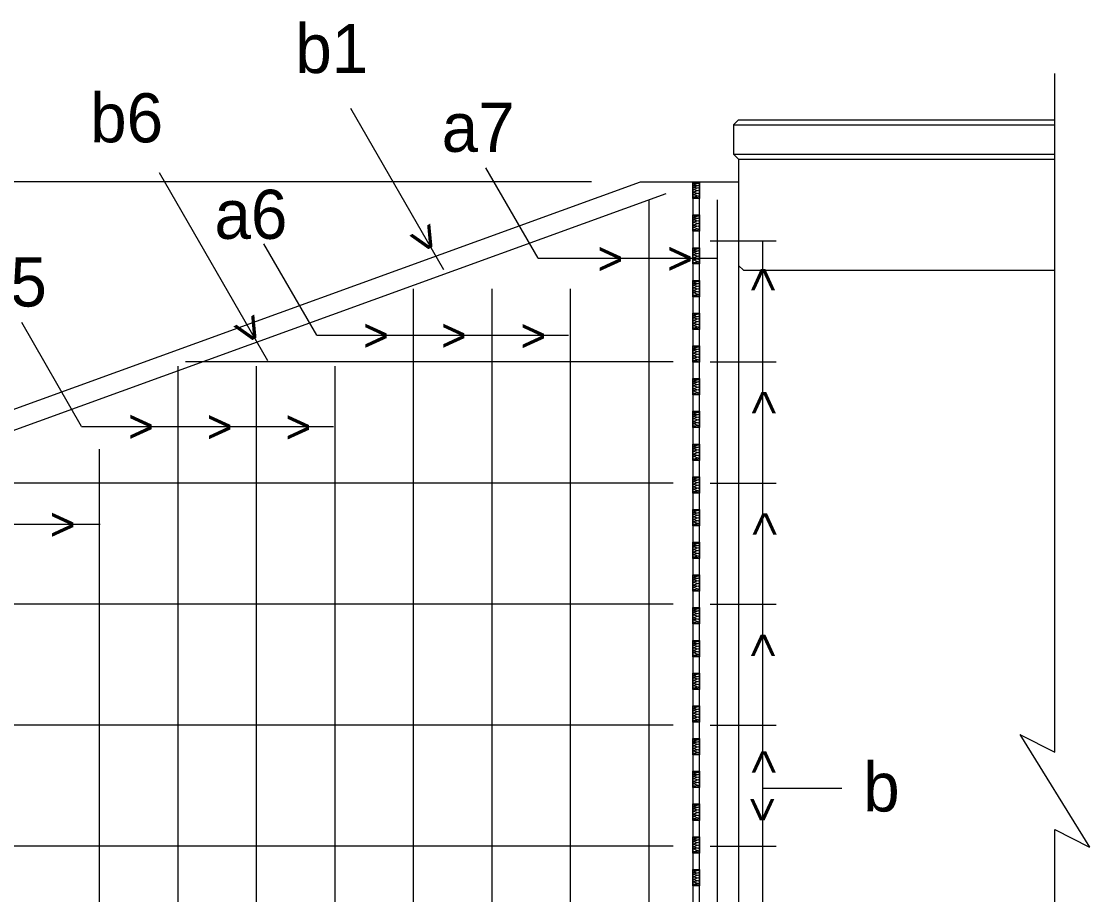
# Model space of a CAD drawing. Extents: x -0.08 to 2.83, y -0.03 to 1.92.
# Drawn here: x 0.6457 to 0.9292, y 0.8025 to 1.0342 of the extents above; entities that cross this region are included whole.
import ezdxf

# ---------------------------------------------------------------- set-up
doc = ezdxf.new("R2010")
doc.units = 0
for name, color, linetype in [('1', 7, 'Continuous'), ('50', 7, 'Continuous'), ('51', 7, 'Continuous'), ('55', 7, 'Continuous'), ('57', 7, 'Continuous')]:
    doc.layers.add(name, color=color, linetype=linetype)

msp = doc.modelspace()

# ---------------------------------------------------------------- linework, layer by layer
at = {"layer": '1'}
for points in [[(0.82387, 0.98719), (0.82387, 0.99152), (0.8256, 0.99152), (0.8256, 0.98719)], [(0.82387, 0.9785), (0.82387, 0.98284), (0.8256, 0.98284), (0.8256, 0.9785)], [(0.82387, 0.96983), (0.82387, 0.97416), (0.8256, 0.97416), (0.8256, 0.96983)], [(0.82387, 0.96114), (0.82387, 0.96548), (0.8256, 0.96548), (0.8256, 0.96114)], [(0.82387, 0.95246), (0.82387, 0.9568), (0.8256, 0.9568), (0.8256, 0.95246)], [(0.82387, 0.94379), (0.82387, 0.94812), (0.8256, 0.94812), (0.8256, 0.94379)], [(0.82387, 0.9351), (0.82387, 0.93944), (0.8256, 0.93944), (0.8256, 0.9351)], [(0.82387, 0.92642), (0.82387, 0.93076), (0.8256, 0.93076), (0.8256, 0.92642)], [(0.82387, 0.91774), (0.82387, 0.92208), (0.8256, 0.92208), (0.8256, 0.91774)], [(0.82387, 0.90906), (0.82387, 0.91339), (0.8256, 0.91339), (0.8256, 0.90906)], [(0.82387, 0.90038), (0.82387, 0.90472), (0.8256, 0.90472), (0.8256, 0.90038)], [(0.82387, 0.8917), (0.82387, 0.89604), (0.8256, 0.89604), (0.8256, 0.8917)], [(0.82387, 0.88302), (0.82387, 0.88735), (0.8256, 0.88735), (0.8256, 0.88302)], [(0.82387, 0.87434), (0.82387, 0.87868), (0.8256, 0.87868), (0.8256, 0.87434)], [(0.82387, 0.86566), (0.82387, 0.86999), (0.8256, 0.86999), (0.8256, 0.86566)], [(0.82387, 0.85698), (0.82387, 0.86131), (0.8256, 0.86131), (0.8256, 0.85698)], [(0.82387, 0.84829), (0.82387, 0.85264), (0.8256, 0.85264), (0.8256, 0.84829)], [(0.82387, 0.83962), (0.82387, 0.84395), (0.8256, 0.84395), (0.8256, 0.83962)], [(0.82387, 0.83094), (0.82387, 0.83527), (0.8256, 0.83527), (0.8256, 0.83094)], [(0.82387, 0.82225), (0.82387, 0.82659), (0.8256, 0.82659), (0.8256, 0.82225)], [(0.82387, 0.81358), (0.82387, 0.81791), (0.8256, 0.81791), (0.8256, 0.81358)], [(0.82387, 0.80489), (0.82387, 0.80923), (0.8256, 0.80923), (0.8256, 0.80489)]]:
    msp.add_lwpolyline(points, close=True, dxfattribs=at)
for points in [[(0.82398, 0.99128), (0.8255, 0.99129), (0.82398, 0.99078), (0.82534, 0.99066), (0.82402, 0.99025), (0.82531, 0.98999), (0.82405, 0.98958), (0.82526, 0.98929), (0.82405, 0.98884), (0.82536, 0.98851), (0.82401, 0.98827), (0.82536, 0.98778), (0.82409, 0.98754), (0.82531, 0.98743), (0.82524, 0.98741)], [(0.82398, 0.98259), (0.8255, 0.98261), (0.82398, 0.98209), (0.82534, 0.98198), (0.82402, 0.98157), (0.82531, 0.9813), (0.82405, 0.9809), (0.82526, 0.98061), (0.82405, 0.98016), (0.82536, 0.97983), (0.82401, 0.97959), (0.82536, 0.97909), (0.82409, 0.97886), (0.82531, 0.97874), (0.82524, 0.97873)], [(0.82398, 0.97392), (0.8255, 0.97394), (0.82398, 0.97341), (0.82534, 0.97329), (0.82402, 0.97289), (0.82531, 0.97263), (0.82405, 0.97222), (0.82526, 0.97193), (0.82405, 0.97148), (0.82536, 0.97115), (0.82401, 0.97091), (0.82536, 0.97042), (0.82409, 0.97018), (0.82531, 0.97006), (0.82524, 0.97004)], [(0.82398, 0.96524), (0.8255, 0.96525), (0.82398, 0.96474), (0.82534, 0.96462), (0.82402, 0.96421), (0.82531, 0.96394), (0.82405, 0.96354), (0.82526, 0.96324), (0.82405, 0.96279), (0.82536, 0.96247), (0.82401, 0.96223), (0.82536, 0.96174), (0.82409, 0.9615), (0.82531, 0.96139), (0.82524, 0.96137)], [(0.82398, 0.95655), (0.8255, 0.95657), (0.82398, 0.95605), (0.82534, 0.95594), (0.82402, 0.95553), (0.82531, 0.95526), (0.82405, 0.95486), (0.82526, 0.95457), (0.82405, 0.95412), (0.82536, 0.95379), (0.82401, 0.95355), (0.82536, 0.95305), (0.82409, 0.95282), (0.82531, 0.9527), (0.82524, 0.95269)], [(0.82398, 0.94788), (0.8255, 0.94789), (0.82398, 0.94737), (0.82534, 0.94725), (0.82402, 0.94685), (0.82531, 0.94659), (0.82405, 0.94618), (0.82526, 0.94589), (0.82405, 0.94544), (0.82536, 0.94511), (0.82401, 0.94487), (0.82536, 0.94438), (0.82409, 0.94414), (0.82531, 0.94402), (0.82524, 0.944)], [(0.82398, 0.93919), (0.8255, 0.93921), (0.82398, 0.93869), (0.82534, 0.93858), (0.82402, 0.93817), (0.82531, 0.9379), (0.82405, 0.9375), (0.82526, 0.9372), (0.82405, 0.93675), (0.82536, 0.93643), (0.82401, 0.93619), (0.82536, 0.93569), (0.82409, 0.93546), (0.82531, 0.93534), (0.82524, 0.93533)], [(0.82398, 0.93052), (0.8255, 0.93054), (0.82398, 0.93001), (0.82534, 0.92989), (0.82402, 0.92949), (0.82531, 0.92922), (0.82405, 0.92882), (0.82526, 0.92853), (0.82405, 0.92808), (0.82536, 0.92774), (0.82401, 0.92751), (0.82536, 0.92702), (0.82409, 0.92678), (0.82531, 0.92666), (0.82524, 0.92664)], [(0.82398, 0.92184), (0.8255, 0.92185), (0.82398, 0.92133), (0.82534, 0.92121), (0.82402, 0.92081), (0.82531, 0.92054), (0.82405, 0.92014), (0.82526, 0.91984), (0.82405, 0.91939), (0.82536, 0.91907), (0.82401, 0.91883), (0.82536, 0.91834), (0.82409, 0.91809), (0.82531, 0.91798), (0.82524, 0.91796)], [(0.82398, 0.91315), (0.8255, 0.91317), (0.82398, 0.91265), (0.82534, 0.91254), (0.82402, 0.91213), (0.82531, 0.91186), (0.82405, 0.91146), (0.82526, 0.91116), (0.82405, 0.91071), (0.82536, 0.91039), (0.82401, 0.91014), (0.82536, 0.90965), (0.82409, 0.90942), (0.82531, 0.9093), (0.82524, 0.90929)], [(0.82398, 0.90448), (0.8255, 0.90449), (0.82398, 0.90397), (0.82534, 0.90385), (0.82402, 0.90344), (0.82531, 0.90318), (0.82405, 0.90278), (0.82526, 0.90249), (0.82405, 0.90204), (0.82536, 0.9017), (0.82401, 0.90147), (0.82536, 0.90098), (0.82409, 0.90074), (0.82531, 0.90062), (0.82524, 0.9006)], [(0.82398, 0.89579), (0.8255, 0.89581), (0.82398, 0.89529), (0.82534, 0.89517), (0.82402, 0.89477), (0.82531, 0.8945), (0.82405, 0.89409), (0.82526, 0.8938), (0.82405, 0.89335), (0.82536, 0.89303), (0.82401, 0.89279), (0.82536, 0.89229), (0.82409, 0.89205), (0.82531, 0.89194), (0.82524, 0.89192)], [(0.82398, 0.88711), (0.8255, 0.88713), (0.82398, 0.88661), (0.82534, 0.88649), (0.82402, 0.88609), (0.82531, 0.88582), (0.82405, 0.88542), (0.82526, 0.88512), (0.82405, 0.88467), (0.82536, 0.88434), (0.82401, 0.8841), (0.82536, 0.88361), (0.82409, 0.88338), (0.82531, 0.88326), (0.82524, 0.88324)], [(0.82398, 0.87844), (0.8255, 0.87845), (0.82398, 0.87793), (0.82534, 0.87781), (0.82402, 0.8774), (0.82531, 0.87714), (0.82405, 0.87674), (0.82526, 0.87644), (0.82405, 0.87599), (0.82536, 0.87566), (0.82401, 0.87543), (0.82536, 0.87494), (0.82409, 0.87469), (0.82531, 0.87458), (0.82524, 0.87456)], [(0.82398, 0.86975), (0.8255, 0.86977), (0.82398, 0.86924), (0.82534, 0.86913), (0.82402, 0.86873), (0.82531, 0.86846), (0.82405, 0.86805), (0.82526, 0.86776), (0.82405, 0.86731), (0.82536, 0.86699), (0.82401, 0.86674), (0.82536, 0.86625), (0.82409, 0.86601), (0.82531, 0.86589), (0.82524, 0.86588)], [(0.82398, 0.86107), (0.8255, 0.86109), (0.82398, 0.86057), (0.82534, 0.86045), (0.82402, 0.86004), (0.82531, 0.85978), (0.82405, 0.85938), (0.82526, 0.85908), (0.82405, 0.85863), (0.82536, 0.8583), (0.82401, 0.85806), (0.82536, 0.85757), (0.82409, 0.85734), (0.82531, 0.85722), (0.82524, 0.8572)], [(0.82398, 0.85239), (0.8255, 0.85241), (0.82398, 0.85189), (0.82534, 0.85177), (0.82402, 0.85136), (0.82531, 0.85109), (0.82405, 0.85069), (0.82526, 0.8504), (0.82405, 0.84995), (0.82536, 0.84962), (0.82401, 0.84939), (0.82536, 0.84889), (0.82409, 0.84865), (0.82531, 0.84854), (0.82524, 0.84852)], [(0.82398, 0.84371), (0.8255, 0.84373), (0.82398, 0.8432), (0.82534, 0.84309), (0.82402, 0.84269), (0.82531, 0.84242), (0.82405, 0.84201), (0.82526, 0.84172), (0.82405, 0.84127), (0.82536, 0.84094), (0.82401, 0.8407), (0.82536, 0.84021), (0.82409, 0.83997), (0.82531, 0.83985), (0.82524, 0.83984)], [(0.82398, 0.83503), (0.8255, 0.83504), (0.82398, 0.83453), (0.82534, 0.83441), (0.82402, 0.834), (0.82531, 0.83374), (0.82405, 0.83334), (0.82526, 0.83304), (0.82405, 0.83259), (0.82536, 0.83226), (0.82401, 0.83202), (0.82536, 0.83153), (0.82409, 0.83129), (0.82531, 0.83118), (0.82524, 0.83116)], [(0.82398, 0.82635), (0.8255, 0.82637), (0.82398, 0.82584), (0.82534, 0.82573), (0.82402, 0.82532), (0.82531, 0.82505), (0.82405, 0.82465), (0.82526, 0.82436), (0.82405, 0.82391), (0.82536, 0.82358), (0.82401, 0.82334), (0.82536, 0.82285), (0.82409, 0.82261), (0.82531, 0.82249), (0.82524, 0.82248)], [(0.82398, 0.81767), (0.8255, 0.81769), (0.82398, 0.81716), (0.82534, 0.81704), (0.82402, 0.81664), (0.82531, 0.81638), (0.82405, 0.81597), (0.82526, 0.81568), (0.82405, 0.81523), (0.82536, 0.8149), (0.82401, 0.81466), (0.82536, 0.81417), (0.82409, 0.81393), (0.82531, 0.81381), (0.82524, 0.81379)], [(0.82398, 0.80899), (0.8255, 0.809), (0.82398, 0.80849), (0.82534, 0.80837), (0.82402, 0.80796), (0.82531, 0.80769), (0.82405, 0.80729), (0.82526, 0.80699), (0.82405, 0.80654), (0.82536, 0.80622), (0.82401, 0.80598), (0.82536, 0.80549), (0.82409, 0.80525), (0.82531, 0.80514), (0.82524, 0.80512)]]:
    msp.add_lwpolyline(points, dxfattribs=at)
at = {"layer": '50'}
for p, q in [((0.91992, 0.84038), (0.91992, 1.02037)), ((0.83467, 1.00678), (0.83467, 0.99897)), ((0.83467, 1.00678), (0.91992, 1.00678)), ((0.83601, 1.00808), (0.83469, 1.00676)), ((0.83601, 1.00808), (0.91992, 1.00808)), ((0.83601, 0.99767), (0.83469, 0.99898)), ((0.83474, 0.99897), (0.91992, 0.99897)), ((0.83601, 0.99767), (0.83601, 0.67648)), ((0.83601, 0.99767), (0.91992, 0.99767)), ((0.36955, 0.83186), (0.80997, 0.99159)), ((0.80997, 0.99159), (0.83601, 0.99159)), ((0.82385, 0.99159), (0.82385, 0.98689)), ((0.82559, 0.99159), (0.82559, 0.98689)), ((0.82559, 0.99109), (0.82559, 0.98689)), ((0.37249, 0.82739), (0.81676, 0.98851)), ((0.82385, 0.98689), (0.82385, 0.90749)), ((0.82559, 0.98689), (0.82559, 0.90749)), ((0.82385, 0.9829), (0.82385, 0.97821)), ((0.82559, 0.9829), (0.82559, 0.97821)), ((0.82559, 0.9824), (0.82559, 0.97821)), ((0.82385, 0.97821), (0.82385, 0.97745)), ((0.82559, 0.97821), (0.82559, 0.97745)), ((0.82385, 0.97486), (0.82385, 0.96878)), ((0.82385, 0.97422), (0.82385, 0.96953)), ((0.82559, 0.97486), (0.82559, 0.96878)), ((0.82559, 0.97422), (0.82559, 0.96953)), ((0.82559, 0.97373), (0.82559, 0.96953)), ((0.82385, 0.96953), (0.82385, 0.96878)), ((0.82559, 0.96953), (0.82559, 0.96878)), ((0.83731, 0.96815), (0.83601, 0.96945)), ((0.83731, 0.96815), (0.91992, 0.96815)), ((0.82385, 0.96618), (0.82385, 0.96009)), ((0.82385, 0.96618), (0.82385, 0.96009)), ((0.82385, 0.96554), (0.82385, 0.96085)), ((0.82559, 0.96618), (0.82559, 0.96009)), ((0.82559, 0.96618), (0.82559, 0.96009)), ((0.82559, 0.96554), (0.82559, 0.96085)), ((0.82559, 0.96504), (0.82559, 0.96085)), ((0.82385, 0.96085), (0.82385, 0.96009)), ((0.82559, 0.96085), (0.82559, 0.96009)), ((0.82385, 0.9575), (0.82385, 0.95141)), ((0.82385, 0.9575), (0.82385, 0.95141)), ((0.82385, 0.9575), (0.82385, 0.95141)), ((0.82385, 0.95686), (0.82385, 0.95217)), ((0.82559, 0.9575), (0.82559, 0.95141)), ((0.82559, 0.9575), (0.82559, 0.95141)), ((0.82559, 0.9575), (0.82559, 0.95141)), ((0.82559, 0.95686), (0.82559, 0.95217)), ((0.82559, 0.95636), (0.82559, 0.95217)), ((0.82385, 0.95217), (0.82385, 0.95141)), ((0.82559, 0.95217), (0.82559, 0.95141)), ((0.82385, 0.94818), (0.82385, 0.94349)), ((0.82559, 0.94818), (0.82559, 0.94349)), ((0.82559, 0.94769), (0.82559, 0.94349)), ((0.82385, 0.94349), (0.82385, 0.94274)), ((0.82559, 0.94349), (0.82559, 0.94274)), ((0.82385, 0.94014), (0.82385, 0.93405)), ((0.82385, 0.9395), (0.82385, 0.93481)), ((0.82559, 0.94014), (0.82559, 0.93405)), ((0.82559, 0.9395), (0.82559, 0.93481)), ((0.82559, 0.939), (0.82559, 0.93481)), ((0.82385, 0.93481), (0.82385, 0.93405)), ((0.82559, 0.93481), (0.82559, 0.93405)), ((0.82385, 0.93146), (0.82385, 0.92537)), ((0.82385, 0.93146), (0.82385, 0.92537)), ((0.82385, 0.93082), (0.82385, 0.92613)), ((0.82559, 0.93146), (0.82559, 0.92537)), ((0.82559, 0.93146), (0.82559, 0.92537)), ((0.82559, 0.93082), (0.82559, 0.92613)), ((0.82559, 0.93032), (0.82559, 0.92613)), ((0.82385, 0.92613), (0.82385, 0.92537)), ((0.82559, 0.92613), (0.82559, 0.92537)), ((0.82385, 0.92278), (0.82385, 0.91669)), ((0.82385, 0.92278), (0.82385, 0.91669)), ((0.82385, 0.92278), (0.82385, 0.91669)), ((0.82385, 0.92214), (0.82385, 0.91744)), ((0.82559, 0.92278), (0.82559, 0.91669)), ((0.82559, 0.92278), (0.82559, 0.91669)), ((0.82559, 0.92278), (0.82559, 0.91669)), ((0.82559, 0.92214), (0.82559, 0.91744)), ((0.82559, 0.92164), (0.82559, 0.91744)), ((0.82385, 0.91744), (0.82385, 0.91669)), ((0.82559, 0.91744), (0.82559, 0.91669)), ((0.82385, 0.91346), (0.82385, 0.90877)), ((0.82559, 0.91346), (0.82559, 0.90877)), ((0.82559, 0.91296), (0.82559, 0.90877)), ((0.82385, 0.90877), (0.82385, 0.90801)), ((0.82385, 0.90749), (0.82385, 0.67648)), ((0.82559, 0.90877), (0.82559, 0.90801)), ((0.82559, 0.90749), (0.82559, 0.67642)), ((0.82385, 0.90542), (0.82385, 0.89933)), ((0.82385, 0.90478), (0.82385, 0.90009)), ((0.82559, 0.90542), (0.82559, 0.89933)), ((0.82559, 0.90478), (0.82559, 0.90009)), ((0.82559, 0.90428), (0.82559, 0.90009)), ((0.82385, 0.90009), (0.82385, 0.89933)), ((0.82559, 0.90009), (0.82559, 0.89933)), ((0.82385, 0.89674), (0.82385, 0.89065)), ((0.82385, 0.89674), (0.82385, 0.89065)), ((0.82385, 0.89609), (0.82385, 0.8914)), ((0.82559, 0.89674), (0.82559, 0.89065)), ((0.82559, 0.89674), (0.82559, 0.89065)), ((0.82559, 0.89609), (0.82559, 0.8914)), ((0.82559, 0.8956), (0.82559, 0.8914)), ((0.82385, 0.8914), (0.82385, 0.89065)), ((0.82559, 0.8914), (0.82559, 0.89065)), ((0.82385, 0.88805), (0.82385, 0.88197)), ((0.82385, 0.88805), (0.82385, 0.88197)), ((0.82385, 0.88805), (0.82385, 0.88197)), ((0.82385, 0.88742), (0.82385, 0.88273)), ((0.82559, 0.88805), (0.82559, 0.88197)), ((0.82559, 0.88805), (0.82559, 0.88197)), ((0.82559, 0.88805), (0.82559, 0.88197)), ((0.82559, 0.88742), (0.82559, 0.88273)), ((0.82559, 0.88692), (0.82559, 0.88273)), ((0.82385, 0.88273), (0.82385, 0.88197)), ((0.82559, 0.88273), (0.82559, 0.88197)), ((0.82385, 0.87874), (0.82385, 0.87404)), ((0.82559, 0.87874), (0.82559, 0.87404)), ((0.82559, 0.87824), (0.82559, 0.87404)), ((0.82385, 0.87404), (0.82385, 0.87329)), ((0.82559, 0.87404), (0.82559, 0.87329)), ((0.82385, 0.87069), (0.82385, 0.86461)), ((0.82559, 0.87069), (0.82559, 0.86461)), ((0.82385, 0.87005), (0.82385, 0.86536)), ((0.82559, 0.87005), (0.82559, 0.86536)), ((0.82559, 0.86956), (0.82559, 0.86536)), ((0.82385, 0.86536), (0.82385, 0.86461)), ((0.82559, 0.86536), (0.82559, 0.86461)), ((0.82385, 0.86201), (0.82385, 0.85593)), ((0.82385, 0.86201), (0.82385, 0.85593)), ((0.82559, 0.86201), (0.82559, 0.85593)), ((0.82559, 0.86201), (0.82559, 0.85593)), ((0.82385, 0.86138), (0.82385, 0.85669)), ((0.82559, 0.86138), (0.82559, 0.85669)), ((0.82559, 0.86088), (0.82559, 0.85669)), ((0.82385, 0.85669), (0.82385, 0.85593)), ((0.82559, 0.85669), (0.82559, 0.85593)), ((0.82385, 0.85334), (0.82385, 0.84724)), ((0.82385, 0.85334), (0.82385, 0.84724)), ((0.82385, 0.85334), (0.82385, 0.84724)), ((0.82559, 0.85334), (0.82559, 0.84724)), ((0.82559, 0.85334), (0.82559, 0.84724)), ((0.82559, 0.85334), (0.82559, 0.84724)), ((0.82385, 0.85269), (0.82385, 0.848)), ((0.82559, 0.85269), (0.82559, 0.848)), ((0.82559, 0.85219), (0.82559, 0.848)), ((0.82385, 0.848), (0.82385, 0.84724)), ((0.82559, 0.848), (0.82559, 0.84724)), ((0.82385, 0.84401), (0.82385, 0.83932)), ((0.82559, 0.84401), (0.82559, 0.83932)), ((0.82559, 0.84352), (0.82559, 0.83932)), ((0.82385, 0.83932), (0.82385, 0.83857)), ((0.82559, 0.83932), (0.82559, 0.83857)), ((0.82385, 0.83597), (0.82385, 0.82989)), ((0.82385, 0.83534), (0.82385, 0.83064)), ((0.82559, 0.83597), (0.82559, 0.82989)), ((0.82559, 0.83534), (0.82559, 0.83064)), ((0.82559, 0.83484), (0.82559, 0.83064)), ((0.82385, 0.83064), (0.82385, 0.82989)), ((0.82559, 0.83064), (0.82559, 0.82989)), ((0.82385, 0.82729), (0.82385, 0.8212)), ((0.82385, 0.82729), (0.82385, 0.8212)), ((0.82385, 0.82665), (0.82385, 0.82196)), ((0.82559, 0.82729), (0.82559, 0.8212)), ((0.82559, 0.82729), (0.82559, 0.8212)), ((0.82559, 0.82665), (0.82559, 0.82196)), ((0.82559, 0.82615), (0.82559, 0.82196)), ((0.82385, 0.82196), (0.82385, 0.8212)), ((0.82385, 0.82084), (0.82385, 0.81599)), ((0.82385, 0.82009), (0.82385, 0.8155)), ((0.82559, 0.82196), (0.82559, 0.8212)), ((0.82559, 0.82084), (0.82559, 0.81599)), ((0.82559, 0.82034), (0.82559, 0.81599)), ((0.82559, 0.82009), (0.82559, 0.8155)), ((0.82559, 0.81959), (0.82559, 0.8155)), ((0.91992, 0.63423), (0.91992, 0.81979)), ((0.82385, 0.81861), (0.82385, 0.81253)), ((0.82385, 0.81861), (0.82385, 0.81253)), ((0.82385, 0.81861), (0.82385, 0.81253)), ((0.82385, 0.81797), (0.82385, 0.81328)), ((0.82559, 0.81861), (0.82559, 0.81253)), ((0.82559, 0.81861), (0.82559, 0.81253)), ((0.82559, 0.81861), (0.82559, 0.81253)), ((0.82559, 0.81797), (0.82559, 0.81328)), ((0.82559, 0.81748), (0.82559, 0.81328)), ((0.82385, 0.81328), (0.82385, 0.81253)), ((0.82559, 0.81328), (0.82559, 0.81253)), ((0.82385, 0.80929), (0.82385, 0.8046)), ((0.82559, 0.80929), (0.82559, 0.8046)), ((0.82559, 0.80879), (0.82559, 0.8046)), ((0.82385, 0.8046), (0.82385, 0.80384)), ((0.82559, 0.8046), (0.82559, 0.80384))]:
    msp.add_line(p, q, dxfattribs=at)
at = {"layer": '51'}
for p, q in [((0.81226, 0.65044), (0.81226, 0.98682)), ((0.83039, 0.65044), (0.83039, 0.98682)), ((0.82847, 0.97595), (0.84599, 0.97595)), ((0.74976, 0.65044), (0.74976, 0.96326)), ((0.77059, 0.65044), (0.77059, 0.96326)), ((0.79143, 0.65044), (0.79143, 0.96326)), ((0.68726, 0.65044), (0.68726, 0.94275)), ((0.81864, 0.94384), (0.68924, 0.94384)), ((0.70809, 0.65044), (0.70809, 0.94275)), ((0.72893, 0.65044), (0.72893, 0.94275)), ((0.82847, 0.94384), (0.84599, 0.94384)), ((0.84122, 0.94384), (0.84122, 0.94384)), ((0.66643, 0.65044), (0.66643, 0.92069)), ((0.81864, 0.91172), (0.60129, 0.91172)), ((0.82847, 0.91172), (0.84599, 0.91172)), ((0.84122, 0.91172), (0.84122, 0.91172)), ((0.81864, 0.8796), (0.51335, 0.8796)), ((0.82847, 0.8796), (0.84599, 0.8796)), ((0.84122, 0.8796), (0.84122, 0.8796)), ((0.81864, 0.84749), (0.42799, 0.84749)), ((0.82847, 0.84749), (0.84599, 0.84749)), ((0.84122, 0.84749), (0.84122, 0.84749)), ((0.81864, 0.81537), (0.37281, 0.81537)), ((0.82847, 0.81537), (0.84599, 0.81537)), ((0.84122, 0.81537), (0.84122, 0.81537))]:
    msp.add_line(p, q, dxfattribs=at)
at = {"layer": '55'}
for p, q in [((0.7578, 0.96826), (0.73309, 1.01104)), ((0.78279, 0.97134), (0.76891, 0.99538)), ((0.71111, 0.94416), (0.68233, 0.99399)), ((0.79701, 0.99159), (0.27695, 0.99159)), ((0.72409, 0.95093), (0.71007, 0.97519)), ((0.84244, 0.68689), (0.84244, 0.97595)), ((0.78279, 0.97134), (0.83039, 0.97134)), ((0.66168, 0.92675), (0.64578, 0.95429)), ((0.72409, 0.95093), (0.7909, 0.95093)), ((0.66168, 0.92675), (0.72849, 0.92675)), ((0.59977, 0.90078), (0.66659, 0.90078)), ((0.91067, 0.845), (0.91992, 0.84038)), ((0.91067, 0.845), (0.92917, 0.81517)), ((0.84257, 0.83083), (0.8634, 0.83083)), ((0.91992, 0.81979), (0.92917, 0.81517))]:
    msp.add_line(p, q, dxfattribs=at)

# ---------------------------------------------------------------- texts
for rotation, p in [(300.0268, (0.74754, 0.97737)), (300.0268, (0.74754, 0.97737)), (90, (0.84666, 0.96225)), (90, (0.84666, 0.96225)), (300.0452, (0.70084, 0.95326)), (300.0452, (0.70084, 0.95326)), (300.0452, (0.70084, 0.95326)), (300.0452, (0.70084, 0.95326)), (90, (0.84687, 0.92965)), (90, (0.84687, 0.92965)), (90, (0.84709, 0.89748)), (90, (0.84709, 0.89748)), (90, (0.84665, 0.8653)), (90, (0.84665, 0.8653)), (90, (0.84685, 0.83434)), (90, (0.84685, 0.83434)), (270, (0.83814, 0.82847)), (270, (0.83814, 0.82847))]:
    msp.add_text('>', height=0.00868, rotation=rotation, dxfattribs=at).set_placement(p)
for p in [(0.79861, 0.96699), (0.79861, 0.96699), (0.81705, 0.96705), (0.81705, 0.96705), (0.73639, 0.94664), (0.73639, 0.94664), (0.75705, 0.94665), (0.75705, 0.94665), (0.77815, 0.94656), (0.77815, 0.94656), (0.67404, 0.92249), (0.67404, 0.92249), (0.69491, 0.9224), (0.69491, 0.9224), (0.71582, 0.92234), (0.71582, 0.92234), (0.65324, 0.89651), (0.65324, 0.89651)]:
    msp.add_text('>', height=0.00868, dxfattribs=at).set_placement(p)
at = {"layer": '57'}
for s, height, p in [('b1', 0.013017, (0.71838, 1.02048)), ('b6', 0.013017, (0.66394, 1.0021)), ('a7', 0.013017, (0.75722, 0.99958)), ('a6', 0.013017, (0.69692, 0.9765)), ('a5', 0.013017, (0.63308, 0.95855)), ('b', 0.01302, (0.86908, 0.8246))]:
    msp.add_text(s, height=height, dxfattribs=at).set_placement(p)

doc.saveas('drawing.dxf')
